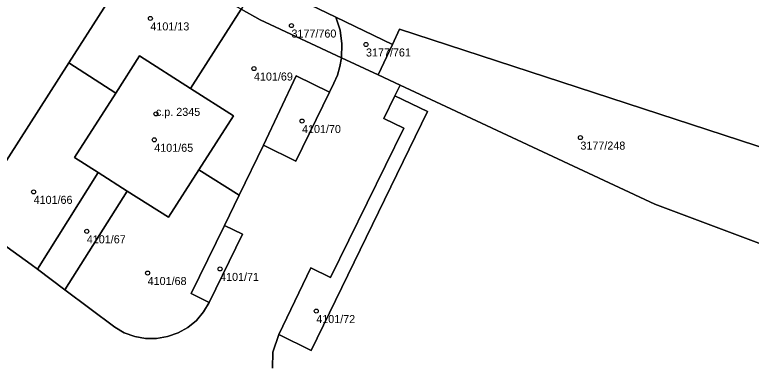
# Model space of a CAD drawing. Extents: x -878211 to -870363, y -1058464 to -1052522.
# Drawn here: x -874043.9 to -873952.4, y -1057145.9 to -1057102.1 of the extents above; entities that cross this region are included whole.
import ezdxf

# ---------------------------------------------------------------- set-up
doc = ezdxf.new("R2010")
doc.units = 0
for name, color, linetype in [('Definiční body', 7, 'Continuous'), ('Polygon budovy', 7, 'Continuous'), ('Polygon parcely', 7, 'Continuous')]:
    doc.layers.add(name, color=color, linetype=linetype)

msp = doc.modelspace()

# ---------------------------------------------------------------- linework, layer by layer
at = {"layer": 'Definiční body'}
for centre in [(-874027.02, -1057102.60994), (-874009.49, -1057103.49994), (-874000.23, -1057105.84994), (-874014.15, -1057108.83994), (-874026.33, -1057114.46994), (-874008.18, -1057115.35994), (-873973.59, -1057117.41994), (-874026.54, -1057117.68994), (-874041.53, -1057124.15994), (-874034.92, -1057129.05994), (-874018.36, -1057133.72994), (-874027.36, -1057134.23994), (-874006.41, -1057138.96994)]:
    msp.add_circle(centre, 0.25, dxfattribs=at)
at = {"layer": 'Polygon budovy'}
msp.add_lwpolyline([(-874031.32, -1057111.88), (-874036.43, -1057119.88), (-874033.49, -1057121.75), (-874029.89, -1057124.05), (-874024.78, -1057127.31), (-874021, -1057121.4), (-874016.71, -1057114.7), (-874022.05, -1057111.3), (-874028.37, -1057107.27)], close=True, dxfattribs=at)
at = {"layer": 'Polygon parcely'}
for points in [[(-874044.25, -1057082.63), (-874030.48, -1057089.65), (-874026.55, -1057091.55), (-874013.45, -1057097.87), (-874003.97, -1057102.44), (-873996.93, -1057105.83), (-873996.05, -1057103.95), (-873943.69, -1057121.04), (-873943.45, -1057114.57), (-873943.37, -1057112.53), (-873943.23, -1057108.82), (-873943.19, -1057107.81), (-873914.96, -1057108.87), (-873885.69, -1057109.97), (-873885.91, -1057116.71), (-873882.01, -1057116.86), (-873881.76, -1057116.96), (-873878.4, -1057118.25), (-873876.38, -1057121.55), (-873873.72, -1057133.12), (-873870.17, -1057148.52)], [(-874011.86, -1057146.07), (-874011.79, -1057144.08), (-874011.08, -1057141.88), (-874007.07, -1057133.58), (-874004.64, -1057134.78), (-873995.54, -1057116.24), (-873998.01, -1057115.04), (-873996.63, -1057112.21), (-873995.99, -1057110.9), (-873998.7, -1057109.63), (-874003.28, -1057107.49), (-874003.47, -1057108.58), (-874003.79, -1057109.64), (-874004.21, -1057110.65), (-874004.75, -1057111.75), (-874008.93, -1057120.34), (-874012.98, -1057118.37), (-874016, -1057124.58), (-874017.83, -1057128.34), (-874015.59, -1057129.43), (-874019.71, -1057137.9), (-874020.41, -1057139.08), (-874021.31, -1057140.12), (-874022.38, -1057141), (-874023.58, -1057141.67), (-874024.88, -1057142.13), (-874026.24, -1057142.37), (-874027.62, -1057142.36), (-874028.97, -1057142.12), (-874030.27, -1057141.65), (-874031.43, -1057140.98), (-874037.63, -1057136.34), (-874041.06, -1057133.77), (-874041.85, -1057133.18), (-874049.63, -1057127.61)], [(-873888.19, -1057149.75), (-873909.17, -1057145.51), (-873914.23, -1057144.49), (-873926.69, -1057139.81), (-873944.14, -1057133.26), (-873964.36, -1057125.67), (-873995.99, -1057110.9), (-873996.63, -1057112.21), (-873992.58, -1057114.18), (-874007.03, -1057143.85), (-874011.08, -1057141.88), (-874011.79, -1057144.08), (-874011.86, -1057146.07)]]:
    msp.add_lwpolyline(points, dxfattribs=at)
for points in [[(-874028.45, -1057094.52), (-874045.76, -1057085.02), (-874066.14, -1057117.14), (-874049.63, -1057127.61), (-874037.16, -1057108.13)], [(-874037.16, -1057108.13), (-874031.32, -1057111.88), (-874028.37, -1057107.27), (-874022.05, -1057111.3), (-874015.76, -1057101.47), (-874028.45, -1057094.52)], [(-874013.4, -1057102.77), (-874003.28, -1057107.49), (-874003.22, -1057105.77), (-874003.45, -1057104.07), (-874003.97, -1057102.44), (-874013.45, -1057097.87), (-874015.76, -1057101.47)], [(-874008.89, -1057109.75), (-874004.75, -1057111.75), (-874004.21, -1057110.65), (-874003.79, -1057109.64), (-874003.47, -1057108.58), (-874003.28, -1057107.49), (-874013.4, -1057102.77), (-874015.76, -1057101.47), (-874022.05, -1057111.3), (-874016.71, -1057114.7), (-874021, -1057121.4), (-874016, -1057124.58), (-874012.98, -1057118.37)], [(-873996.93, -1057105.83), (-874003.97, -1057102.44), (-874003.45, -1057104.07), (-874003.22, -1057105.77), (-874003.28, -1057107.49), (-873998.7, -1057109.63)], [(-873996.93, -1057105.83), (-873998.7, -1057109.63), (-873995.99, -1057110.9), (-873964.36, -1057125.67), (-873944.14, -1057133.26), (-873943.89, -1057126.5), (-873943.69, -1057121.04), (-873996.05, -1057103.95)], [(-874021, -1057121.4), (-874016.71, -1057114.7), (-874022.05, -1057111.3), (-874028.37, -1057107.27), (-874031.32, -1057111.88), (-874036.43, -1057119.88), (-874033.49, -1057121.75), (-874029.89, -1057124.05), (-874024.78, -1057127.31)], [(-874033.49, -1057121.75), (-874036.43, -1057119.88), (-874031.32, -1057111.88), (-874037.16, -1057108.13), (-874049.63, -1057127.61), (-874041.85, -1057133.18), (-874041.06, -1057133.77)], [(-874012.98, -1057118.37), (-874008.93, -1057120.34), (-874004.75, -1057111.75), (-874008.89, -1057109.75)], [(-873996.63, -1057112.21), (-873998.01, -1057115.04), (-873995.54, -1057116.24), (-874004.64, -1057134.78), (-874007.07, -1057133.58), (-874011.08, -1057141.88), (-874007.03, -1057143.85), (-873992.58, -1057114.18)], [(-874037.63, -1057136.34), (-874029.89, -1057124.05), (-874033.49, -1057121.75), (-874041.06, -1057133.77)], [(-874016, -1057124.58), (-874021, -1057121.4), (-874024.78, -1057127.31), (-874029.89, -1057124.05), (-874037.63, -1057136.34), (-874031.43, -1057140.98), (-874030.27, -1057141.65), (-874028.97, -1057142.12), (-874027.62, -1057142.36), (-874026.24, -1057142.37), (-874024.88, -1057142.13), (-874023.58, -1057141.67), (-874022.38, -1057141), (-874021.31, -1057140.12), (-874020.41, -1057139.08), (-874019.71, -1057137.9), (-874021.95, -1057136.8), (-874017.83, -1057128.34)], [(-874021.95, -1057136.8), (-874019.71, -1057137.9), (-874015.59, -1057129.43), (-874017.83, -1057128.34)]]:
    msp.add_lwpolyline(points, close=True, dxfattribs=at)

# ---------------------------------------------------------------- texts
at = {"layer": 'Definiční body'}
for s, p in [('4101/13', (-874027.02, -1057104.099)), ('3177/760', (-874009.49, -1057104.989)), ('3177/761', (-874000.23, -1057107.339)), ('4101/69', (-874014.15, -1057110.329)), ('c.p. 2345', (-874026.33, -1057114.72)), ('4101/70', (-874008.18, -1057116.849)), ('4101/65', (-874026.54, -1057119.179)), ('3177/248', (-873973.59, -1057118.909)), ('4101/66', (-874041.53, -1057125.649)), ('4101/67', (-874034.92, -1057130.549)), ('4101/71', (-874018.36, -1057135.219)), ('4101/68', (-874027.36, -1057135.729)), ('4101/72', (-874006.41, -1057140.459))]:
    msp.add_text(s, height=0.999996, dxfattribs=at).set_placement(p)

doc.saveas('drawing.dxf')
